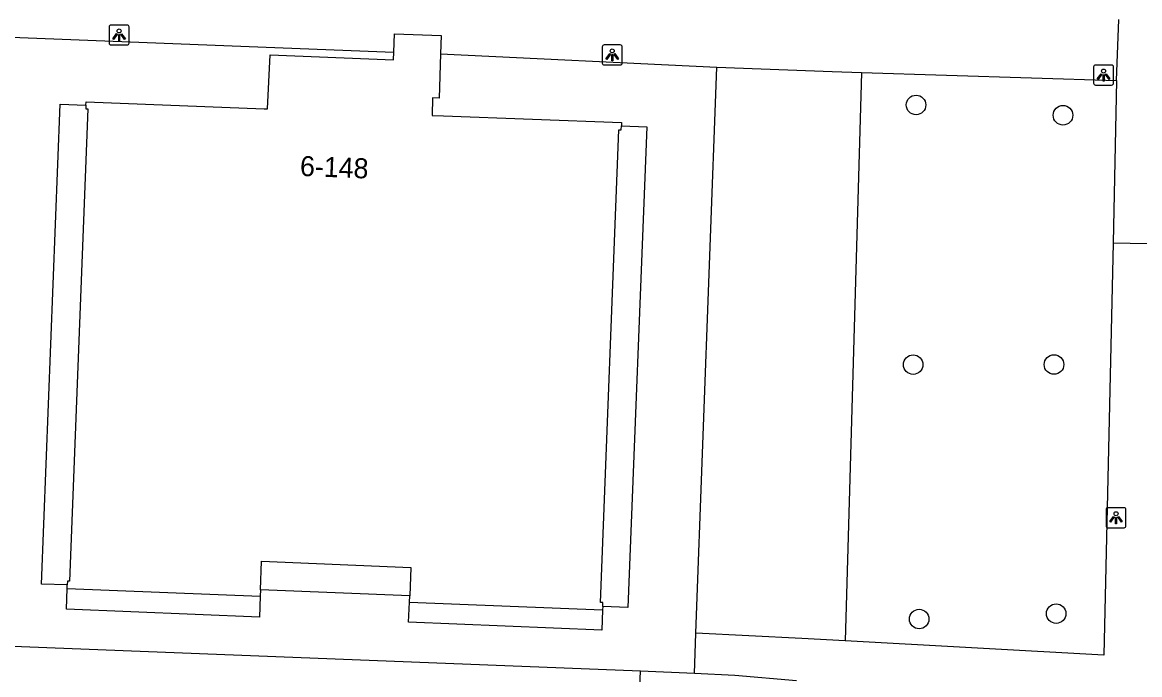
# Model space of a CAD drawing. Extents: x 160077 to 160945, y 386481 to 387498.
# Drawn here: x 160662.6 to 160718.4, y 386545.9 to 386578.5 of the extents above; entities that cross this region are included whole.
import ezdxf

# ---------------------------------------------------------------- set-up
doc = ezdxf.new("R2010")
doc.units = 0
for name, color, linetype in [('IMGEO_Boom', 7, 'Continuous'), ('IMGEO_Groenvoorziening', 7, 'Continuous'), ('IMGEO_Lichtpunt', 7, 'Continuous'), ('IMGEO_Pand', 7, 'Continuous'), ('IMGEO_Pand_nummerreeks', 7, 'Continuous'), ('IMGEO_Voetpad_halfverhard', 7, 'Continuous'), ('IMGEO_Voetpad_open', 7, 'Continuous')]:
    doc.layers.add(name, color=color, linetype=linetype)

msp = doc.modelspace()

# ---------------------------------------------------------------- linework, layer by layer
at = {"layer": 'IMGEO_Boom'}
for centre in [(160707.19, 386574.406), (160714.529, 386573.891), (160707.045, 386561.426), (160714.08, 386561.432), (160714.189, 386548.985), (160707.346, 386548.713)]:
    msp.add_circle(centre, 0.489, dxfattribs=at)
at = {"layer": 'IMGEO_Groenvoorziening'}
msp.add_lwpolyline([(160704.462, 386576.027), (160703.656, 386547.616)], dxfattribs=at)
at = {"layer": 'IMGEO_Lichtpunt'}
for p, q in [((160667.79, 386578.399), (160666.982, 386578.399)), ((160667.79, 386578.399), (160666.982, 386578.399)), ((160666.888, 386578.304), (160666.888, 386577.497)), ((160666.888, 386578.304), (160666.888, 386577.497)), ((160667.884, 386577.497), (160667.884, 386578.304)), ((160667.884, 386577.497), (160667.884, 386578.304)), ((160666.982, 386577.403), (160667.79, 386577.403)), ((160666.982, 386577.403), (160667.79, 386577.403)), ((160691.515, 386577.308), (160691.515, 386576.501)), ((160691.515, 386577.308), (160691.515, 386576.501)), ((160692.417, 386577.403), (160691.609, 386577.403)), ((160692.417, 386577.403), (160691.609, 386577.403)), ((160692.511, 386576.501), (160692.511, 386577.308)), ((160692.511, 386576.501), (160692.511, 386577.308)), ((160691.609, 386576.407), (160692.417, 386576.407)), ((160691.609, 386576.407), (160692.417, 386576.407)), ((160716.055, 386576.302), (160716.055, 386575.495)), ((160716.055, 386576.302), (160716.055, 386575.495)), ((160716.957, 386576.397), (160716.149, 386576.397)), ((160716.957, 386576.397), (160716.149, 386576.397)), ((160717.051, 386575.495), (160717.051, 386576.302)), ((160717.051, 386575.495), (160717.051, 386576.302)), ((160716.149, 386575.401), (160716.957, 386575.401)), ((160716.149, 386575.401), (160716.957, 386575.401)), ((160716.679, 386554.179), (160716.679, 386553.372)), ((160716.679, 386554.179), (160716.679, 386553.372)), ((160717.581, 386554.274), (160716.773, 386554.274)), ((160717.581, 386554.274), (160716.773, 386554.274)), ((160717.675, 386553.372), (160717.675, 386554.179)), ((160717.675, 386553.372), (160717.675, 386554.179)), ((160716.773, 386553.278), (160717.581, 386553.278)), ((160716.773, 386553.278), (160717.581, 386553.278))]:
    msp.add_line(p, q, dxfattribs=at)
for points in [[(160667.262, 386577.968), (160667.301, 386577.94), (160667.113, 386577.678), (160667.075, 386577.705), (160667.262, 386577.968)], [(160667.364, 386577.92), (160667.411, 386577.92), (160667.411, 386577.598), (160667.364, 386577.598), (160667.364, 386577.92)], [(160667.474, 386577.94), (160667.512, 386577.967), (160667.699, 386577.705), (160667.66, 386577.677), (160667.474, 386577.94)], [(160691.889, 386576.972), (160691.928, 386576.944), (160691.74, 386576.682), (160691.702, 386576.709), (160691.889, 386576.972)], [(160691.991, 386576.924), (160692.038, 386576.924), (160692.038, 386576.602), (160691.991, 386576.602), (160691.991, 386576.924)], [(160692.101, 386576.944), (160692.139, 386576.971), (160692.326, 386576.709), (160692.287, 386576.681), (160692.101, 386576.944)], [(160716.429, 386575.966), (160716.468, 386575.938), (160716.28, 386575.676), (160716.242, 386575.703), (160716.429, 386575.966)], [(160716.531, 386575.918), (160716.578, 386575.918), (160716.578, 386575.596), (160716.531, 386575.596), (160716.531, 386575.918)], [(160716.641, 386575.938), (160716.679, 386575.965), (160716.866, 386575.703), (160716.827, 386575.675), (160716.641, 386575.938)], [(160717.053, 386553.843), (160717.092, 386553.815), (160716.904, 386553.553), (160716.866, 386553.58), (160717.053, 386553.843)], [(160717.265, 386553.815), (160717.303, 386553.842), (160717.49, 386553.58), (160717.451, 386553.552), (160717.265, 386553.815)], [(160717.155, 386553.795), (160717.202, 386553.795), (160717.202, 386553.473), (160717.155, 386553.473), (160717.155, 386553.795)]]:
    msp.add_lwpolyline(points, dxfattribs=at)
for centre in [(160667.387, 386578.102), (160692.014, 386577.106), (160716.554, 386576.1), (160717.178, 386553.977)]:
    msp.add_circle(centre, 0.0994, dxfattribs=at)
for centre, start, end in [((160666.982, 386578.304), 90, 180), ((160666.982, 386578.304), 90, 180), ((160667.79, 386578.304), 0, 90), ((160667.79, 386578.304), 0, 90), ((160666.982, 386577.497), 180, 270), ((160666.982, 386577.497), 180, 270), ((160667.79, 386577.497), 270, 0), ((160667.79, 386577.497), 270, 360), ((160691.609, 386577.308), 90, 180), ((160691.609, 386577.308), 90, 180), ((160692.417, 386577.308), 0, 90), ((160692.417, 386577.308), 0, 90), ((160691.609, 386576.501), 180, 270), ((160691.609, 386576.501), 180, 270), ((160692.417, 386576.501), 270, 0), ((160692.417, 386576.501), 270, 360), ((160716.149, 386576.302), 90, 180), ((160716.149, 386576.302), 90, 180), ((160716.957, 386576.302), 0, 90), ((160716.957, 386576.302), 0, 90), ((160716.149, 386575.495), 180, 270), ((160716.149, 386575.495), 180, 270), ((160716.957, 386575.495), 270, 0), ((160716.957, 386575.495), 270, 360), ((160716.773, 386554.179), 90, 180), ((160716.773, 386554.179), 90, 180), ((160717.581, 386554.179), 0, 90), ((160717.581, 386554.179), 0, 90), ((160716.773, 386553.372), 180, 270), ((160716.773, 386553.372), 180, 270), ((160717.581, 386553.372), 270, 0), ((160717.581, 386553.372), 270, 360)]:
    msp.add_arc(centre, 0.0946, start, end, dxfattribs=at)
at = {"layer": 'IMGEO_Pand'}
for points in [[(160681.104, 386577.049), (160681.135, 386577.953), (160683.465, 386577.873), (160683.435, 386576.959)], [(160665.729, 386574.389), (160665.736, 386574.568), (160674.632, 386574.212), (160674.798, 386574.209), (160674.925, 386576.902), (160681.091, 386576.654), (160681.104, 386577.049)], [(160683.435, 386576.959), (160683.364, 386574.746), (160683.044, 386574.757), (160683.016, 386573.883), (160683.596, 386573.862), (160692.482, 386573.522), (160692.47, 386573.359)], [(160665.729, 386574.389), (160665.722, 386574.208), (160665.832, 386574.204), (160664.913, 386550.598), (160664.803, 386550.602), (160664.796, 386550.421)], [(160691.539, 386549.345), (160691.543, 386549.538), (160691.434, 386549.543), (160692.346, 386573.164), (160692.455, 386573.156), (160692.47, 386573.359)], [(160674.446, 386550.169), (160674.503, 386551.598), (160681.957, 386551.295), (160681.899, 386549.866)], [(160664.789, 386550.242), (160664.796, 386550.421)], [(160664.789, 386550.242), (160674.434, 386549.859)], [(160674.446, 386550.169), (160674.434, 386549.859)], [(160681.886, 386549.556), (160681.899, 386549.866)], [(160681.886, 386549.556), (160691.531, 386549.173)], [(160691.539, 386549.345), (160691.531, 386549.173)]]:
    msp.add_lwpolyline(points, dxfattribs=at)
at = {"layer": 'IMGEO_Voetpad_halfverhard'}
for points in [[(160717.031, 386567.517), (160716.577, 386546.91), (160703.656, 386547.616)], [(160703.656, 386547.616), (160701.483, 386547.735), (160696.192, 386548.013)], [(160693.006, 386536.92), (160693.42, 386546.101)], [(160701.218, 386545.623), (160698.138, 386545.898), (160696.118, 386545.994)]]:
    msp.add_lwpolyline(points, dxfattribs=at)
at = {"layer": 'IMGEO_Voetpad_open'}
for points in [[(160717.209, 386575.623), (160717.32, 386578.668)], [(160661.137, 386577.82), (160681.104, 386577.049)], [(160683.435, 386576.959), (160697.234, 386576.285)], [(160696.192, 386548.013), (160697.234, 386576.285)], [(160697.234, 386576.285), (160703.006, 386576.073), (160704.462, 386576.027)], [(160704.462, 386576.027), (160717.209, 386575.623)], [(160717.209, 386575.623), (160717.031, 386567.517)], [(160664.796, 386550.421), (160663.51, 386550.45), (160664.444, 386574.439), (160665.729, 386574.389)], [(160692.47, 386573.359), (160693.739, 386573.315), (160692.798, 386549.297), (160691.539, 386549.345)], [(160717.031, 386567.517), (160719.578, 386567.461)], [(160674.434, 386549.859), (160674.397, 386548.813), (160664.752, 386549.208), (160664.789, 386550.242)], [(160681.899, 386549.866), (160674.446, 386550.169)], [(160691.531, 386549.173), (160691.494, 386548.158), (160681.845, 386548.553), (160681.886, 386549.556)], [(160696.118, 386545.994), (160696.192, 386548.013)], [(160693.42, 386546.101), (160659.943, 386547.427)], [(160696.118, 386545.994), (160693.42, 386546.101)]]:
    msp.add_lwpolyline(points, dxfattribs=at)

# ---------------------------------------------------------------- texts
at = {"layer": 'IMGEO_Pand_nummerreeks'}
msp.add_text('6-148', height=1, rotation=357.764, dxfattribs=at).set_placement((160676.405, 386570.86))

doc.saveas('drawing.dxf')
